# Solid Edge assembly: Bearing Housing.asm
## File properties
Last saved by: Dan
Revision: 65
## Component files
Roller Bearing Housing.par
Cyl Roller 5-8.par
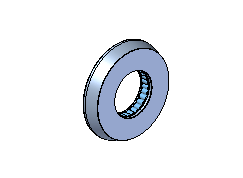
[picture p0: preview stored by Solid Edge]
